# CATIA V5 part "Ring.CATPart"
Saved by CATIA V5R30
Part number: Part1.1
Bounding box of the stored display mesh (mm): x -5 to 5, y -15 to 15, z -15 to 15
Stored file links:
  D:\PROJECTS\CATIA V56R 2020\Resources\Parts File\c12_catia_v5_6r2020_prt\c12_catia_v5-6r2020 figr_12-12\Ring.CATPart
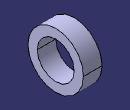
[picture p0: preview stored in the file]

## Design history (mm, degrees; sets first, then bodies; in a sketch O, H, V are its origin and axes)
Body1 (main body)
  Sketch1 on yz-plane, origin (0, 0, 0), H (0, 1, 0), V (0, 0, 1)
    circle A1 centre (0, 0) radius 15
    circle A2 centre (0, 0) radius 10
    radius A1 = 15
    radius A2 = 10
  Pad1: profile Sketch1, direction (1, 0, 0), length 5, mirrored extent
